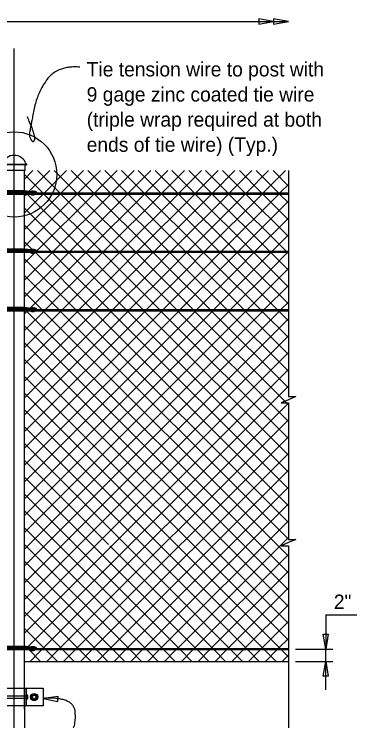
# Model space of a CAD drawing. Extents: x 0 to 41, y -96 to 25.
# Drawn here: x 25.32 to 30.13, y 14.8 to 24.71 of the extents above; entities that cross this region are included whole.
import ezdxf

# ---------------------------------------------------------------- set-up
doc = ezdxf.new("R2010")
doc.units = 0
for name, color, linetype in [('CL_Major', 7, 'Continuous'), ('Dimension', 7, 'Continuous'), ('Miscellaneous', 7, 'Continuous'), ('SteelMisc', 7, 'Continuous'), ('SteelMisc_h', 7, 'Continuous'), ('SupstrConc', 7, 'Continuous')]:
    doc.layers.add(name, color=color, linetype=linetype)

msp = doc.modelspace()

# ---------------------------------------------------------------- linework, layer by layer
at = {"layer": 'CL_Major'}
msp.add_line((25.3238, 9.7541), (25.3238, 24.2317), dxfattribs=at)
at = {"layer": 'Dimension'}
for p, q in [((29.6916, 16.2901), (29.6916, 15.8103)), ((29.6916, 16.2901), (30.1268, 16.2901)), ((29.269, 15.8103), (29.7924, 15.8103)), ((29.6916, 15.6384), (29.6916, 15.8103)), ((29.269, 15.6384), (29.7924, 15.6384)), ((29.6916, 15.2407), (29.6916, 15.6384))]:
    msp.add_line(p, q, dxfattribs=at)
for points in [[(14.3237, 24.6092), (15.7874, 24.6092), (15.7874, 24.7126), (15.8324, 24.6092), (15.8774, 24.5059), (15.8774, 24.6092), (29.1682, 24.6092)], [(29.1682, 22.5181), (29.1682, 19.3509), (29.2716, 19.3509), (29.1682, 19.3059), (29.0649, 19.2609), (29.1682, 19.2609), (29.1682, 18.3673)], [(29.1682, 18.3673), (29.1682, 17.3495), (29.2716, 17.3495), (29.1682, 17.3045), (29.0649, 17.2595), (29.1682, 17.2595), (29.1682, 15.0552)], [(29.1682, 15.3052), (29.1682, 13.4544), (29.2716, 13.4544), (29.1682, 13.4094), (29.0649, 13.3644), (29.1682, 13.3644), (29.1682, 11.8219)]]:
    msp.add_lwpolyline(points, dxfattribs=at)
for points in [[(28.96, 24.6092), (28.7517, 24.6445), (28.7517, 24.5739)], [(29.1682, 24.6092), (28.96, 24.6445), (28.96, 24.5739)], [(29.7269, 16.0185), (29.6916, 15.8103), (29.6563, 16.0185)], [(29.6563, 15.4302), (29.6916, 15.6384), (29.7269, 15.4302)], [(25.7298, 15.1203), (25.9358, 15.074), (25.9396, 15.1444)]]:
    msp.add_lwpolyline(points, close=True, dxfattribs=at)
msp.add_circle((25.3237, 22.4656), 0.5976, dxfattribs=at)
for points in [[(26.2434, 23.9706), (25.9247, 23.9905), (25.6433, 23.6016), (25.5506, 23.1056), (25.5288, 23.0034), (25.5886, 22.9037), (25.6333, 22.9933), (25.5089, 23.2726)], [(26.1714, 14.0966), (25.9344, 14.0943), (26.0058, 14.4456), (26.2043, 14.7506), (26.1489, 15.1434), (25.7297, 15.1203)]]:
    msp.add_open_spline(points, degree=2, dxfattribs=at)
at = {"layer": 'Miscellaneous'}
for p, q in [((25.4696, 22.4004), (25.5873, 22.5181)), ((25.5367, 22.2313), (25.8235, 22.5181)), ((25.65, 22.5181), (25.9625, 22.2055)), ((25.7471, 22.2055), (26.0596, 22.5181)), ((25.8857, 22.5181), (26.1983, 22.2055)), ((25.9833, 22.2055), (26.2958, 22.5181)), ((26.1214, 22.5181), (26.434, 22.2055)), ((26.2194, 22.2055), (26.532, 22.5181)), ((26.3571, 22.5181), (26.6697, 22.2055)), ((26.4556, 22.2055), (26.7682, 22.5181)), ((26.5928, 22.5181), (26.9054, 22.2055)), ((26.6918, 22.2055), (27.0043, 22.5181)), ((26.8285, 22.5181), (27.1411, 22.2055)), ((26.928, 22.2055), (27.2405, 22.5181)), ((27.0642, 22.5181), (27.3768, 22.2055)), ((27.1637, 22.2055), (27.4762, 22.5181)), ((27.2999, 22.5181), (27.6125, 22.2055)), ((27.3994, 22.2055), (27.7119, 22.5181)), ((27.5356, 22.5181), (27.8482, 22.2055)), ((27.6351, 22.2055), (27.9476, 22.5181)), ((27.7713, 22.5181), (28.0839, 22.2055)), ((27.8708, 22.2055), (28.1833, 22.5181)), ((28.0075, 22.5181), (28.32, 22.2055)), ((28.1065, 22.2055), (28.419, 22.5181)), ((28.2437, 22.5181), (28.5562, 22.2055)), ((28.3422, 22.2055), (28.6547, 22.5181)), ((28.4799, 22.5181), (28.7924, 22.2055)), ((28.5779, 22.2055), (28.8904, 22.5181)), ((28.716, 22.5181), (29.0286, 22.2055)), ((28.8136, 22.2055), (29.1261, 22.5181)), ((28.9522, 22.5181), (29.1682, 22.302)), ((25.4696, 22.4628), (25.7268, 22.2055)), ((29.0493, 22.2055), (29.1682, 22.3245)), ((25.4717, 22.225), (25.4911, 22.2055)), ((25.5109, 22.2055), (25.5249, 22.2195)), ((25.4696, 21.4557), (26.2047, 22.1908)), ((25.4696, 21.6919), (25.9685, 22.1908)), ((25.4696, 21.928), (25.7323, 22.1908)), ((25.4696, 22.1642), (25.4962, 22.1908)), ((25.5059, 22.1908), (26.3085, 21.3881)), ((25.6422, 21.3921), (26.4409, 22.1908)), ((25.7416, 22.1908), (26.5442, 21.3881)), ((25.8744, 21.3881), (26.677, 22.1908)), ((25.9773, 22.1908), (26.7799, 21.3881)), ((26.1106, 21.3881), (26.9132, 22.1908)), ((26.213, 22.1908), (27.0157, 21.3881)), ((26.3463, 21.3881), (27.1489, 22.1908)), ((26.4487, 22.1908), (27.2514, 21.3881)), ((26.582, 21.3881), (27.3846, 22.1908)), ((26.6844, 22.1908), (27.4871, 21.3881)), ((26.8177, 21.3881), (27.6203, 22.1908)), ((26.9201, 22.1908), (27.7228, 21.3881)), ((27.0534, 21.3881), (27.856, 22.1908)), ((27.1558, 22.1908), (27.9585, 21.3881)), ((27.2891, 21.3881), (28.0917, 22.1908)), ((27.3915, 22.1908), (28.1942, 21.3881)), ((27.5248, 21.3881), (28.3274, 22.1908)), ((27.6272, 22.1908), (28.4299, 21.3881)), ((27.7605, 21.3881), (28.5631, 22.1908)), ((27.8629, 22.1908), (28.6656, 21.3881)), ((27.9962, 21.3881), (28.7988, 22.1908)), ((28.0986, 22.1908), (28.9013, 21.3881)), ((28.2319, 21.3881), (29.0345, 22.1908)), ((28.3348, 22.1908), (29.1374, 21.3881)), ((28.571, 22.1908), (29.1682, 21.5935)), ((28.8071, 22.1908), (29.1682, 21.8297)), ((29.0433, 22.1908), (29.1682, 22.0659)), ((28.4676, 21.3881), (29.1682, 22.0888)), ((25.4696, 21.9914), (26.0728, 21.3881)), ((28.7033, 21.3881), (29.1682, 21.8531)), ((25.4696, 21.7557), (25.8371, 21.3881)), ((28.939, 21.3881), (29.1682, 21.6174)), ((25.4696, 21.52), (25.5766, 21.413)), ((25.4696, 20.9833), (25.8596, 21.3734)), ((25.4696, 21.2195), (25.6235, 21.3734)), ((25.6162, 21.3734), (26.4196, 20.57)), ((25.8519, 21.3734), (26.0868, 21.1385)), ((25.8609, 21.1385), (26.0958, 21.3734)), ((26.0876, 21.3734), (26.3225, 21.1385)), ((26.0966, 21.1385), (26.3315, 21.3734)), ((26.3233, 21.3734), (26.5582, 21.1385)), ((26.3323, 21.1385), (26.5672, 21.3734)), ((26.559, 21.3734), (26.7939, 21.1385)), ((26.568, 21.1385), (26.8029, 21.3734)), ((26.7947, 21.3734), (27.0296, 21.1385)), ((26.8037, 21.1385), (27.0386, 21.3734)), ((27.0304, 21.3734), (27.2653, 21.1385)), ((27.0394, 21.1385), (27.2743, 21.3734)), ((27.2661, 21.3734), (27.501, 21.1385)), ((27.2751, 21.1385), (27.51, 21.3734)), ((27.5018, 21.3734), (27.7367, 21.1385)), ((27.5108, 21.1385), (27.7457, 21.3734)), ((27.7375, 21.3734), (27.9724, 21.1385)), ((27.7465, 21.1385), (27.9814, 21.3734)), ((27.9732, 21.3734), (28.2081, 21.1385)), ((27.9822, 21.1385), (28.2171, 21.3734)), ((28.2089, 21.3734), (28.4438, 21.1385)), ((28.2179, 21.1385), (28.4528, 21.3734)), ((28.4446, 21.3734), (28.6795, 21.1385)), ((28.4536, 21.1385), (28.6885, 21.3734)), ((28.6803, 21.3734), (28.9152, 21.1385)), ((28.6893, 21.1385), (28.9242, 21.3734)), ((28.916, 21.3734), (29.1682, 21.1212)), ((28.925, 21.1385), (29.1599, 21.3734)), ((29.1522, 21.3734), (29.1682, 21.3573)), ((25.4696, 21.2843), (25.5918, 21.162)), ((25.4696, 21.2843), (26.1839, 20.57)), ((25.4696, 20.7472), (25.8462, 21.1237)), ((25.5526, 20.5944), (26.0966, 21.1385)), ((25.7638, 20.57), (26.3323, 21.1385)), ((25.9995, 20.57), (26.568, 21.1385)), ((26.0868, 21.1385), (26.6553, 20.57)), ((26.2352, 20.57), (26.8037, 21.1385)), ((26.3225, 21.1385), (26.891, 20.57)), ((26.4709, 20.57), (27.0394, 21.1385)), ((26.5582, 21.1385), (27.1267, 20.57)), ((26.7066, 20.57), (27.2751, 21.1385)), ((26.7939, 21.1385), (27.3624, 20.57)), ((26.9423, 20.57), (27.5108, 21.1385)), ((27.0296, 21.1385), (27.5981, 20.57)), ((27.178, 20.57), (27.7465, 21.1385)), ((27.2653, 21.1385), (27.8338, 20.57)), ((27.4137, 20.57), (27.9822, 21.1385)), ((27.501, 21.1385), (28.0695, 20.57)), ((27.6494, 20.57), (28.2179, 21.1385)), ((27.7367, 21.1385), (28.3052, 20.57)), ((27.8851, 20.57), (28.4536, 21.1385)), ((27.9724, 21.1385), (28.5409, 20.57)), ((28.1208, 20.57), (28.6893, 21.1385)), ((28.2081, 21.1385), (28.7766, 20.57)), ((28.3565, 20.57), (28.925, 21.1385)), ((28.4438, 21.1385), (29.0123, 20.57)), ((28.5922, 20.57), (29.1682, 21.146)), ((28.6795, 21.1385), (29.1682, 20.6498)), ((28.9152, 21.1385), (29.1682, 20.8855)), ((25.4696, 21.0486), (25.9482, 20.57)), ((28.8279, 20.57), (29.1682, 20.9103)), ((25.4696, 20.8129), (25.7125, 20.57)), ((29.0636, 20.57), (29.1682, 20.6746)), ((25.4696, 20.5772), (25.4768, 20.57)), ((25.4696, 18.1544), (27.8704, 20.5552)), ((25.4696, 18.6258), (27.3989, 20.5552)), ((25.4696, 19.0972), (26.9275, 20.5552)), ((25.4696, 19.5686), (26.4561, 20.5552)), ((25.4696, 17.683), (28.3418, 20.5552)), ((25.4696, 17.2116), (28.8132, 20.5552)), ((25.4696, 19.8043), (26.2204, 20.5552)), ((25.4696, 19.3329), (26.6918, 20.5552)), ((25.4696, 18.8615), (27.1632, 20.5552)), ((25.4696, 18.3901), (27.6347, 20.5552)), ((25.4696, 17.9187), (28.1061, 20.5552)), ((25.4696, 17.4473), (28.5775, 20.5552)), ((25.4696, 16.9759), (29.0489, 20.5552)), ((25.4696, 20.0401), (25.9847, 20.5552)), ((25.4696, 20.5115), (25.5133, 20.5552)), ((25.474, 20.2802), (25.749, 20.5552)), ((25.4916, 20.5552), (29.1682, 16.8785)), ((25.5281, 20.57), (25.5406, 20.5824)), ((25.7273, 20.5552), (29.1682, 17.1142)), ((25.963, 20.5552), (29.1682, 17.3499)), ((26.1987, 20.5552), (29.1682, 17.5857)), ((26.4344, 20.5552), (29.1682, 17.8214)), ((26.6701, 20.5552), (29.1682, 18.0571)), ((26.9058, 20.5552), (29.1682, 18.2928)), ((27.1415, 20.5552), (29.1682, 18.5285)), ((27.3772, 20.5552), (29.1682, 18.7642)), ((27.6129, 20.5552), (29.1682, 18.9999)), ((27.8486, 20.5552), (29.1682, 19.2356)), ((28.0843, 20.5552), (29.1682, 19.4713)), ((28.32, 20.5552), (29.1682, 19.707)), ((28.5557, 20.5552), (29.1682, 19.9427)), ((28.7914, 20.5552), (29.1682, 20.1784)), ((29.0271, 20.5552), (29.1682, 20.4141)), ((25.4696, 16.7402), (29.1682, 20.4389)), ((25.4696, 20.3415), (29.1682, 16.6428)), ((25.4696, 16.5045), (29.1682, 20.2032)), ((25.4696, 20.1058), (29.1682, 16.4071)), ((25.4696, 16.2688), (29.1682, 19.9675)), ((25.4696, 19.8701), (29.1682, 16.1714)), ((25.4696, 16.0331), (29.1682, 19.7318)), ((25.4696, 19.6344), (29.1682, 15.9357)), ((25.5183, 15.8462), (29.1682, 19.4961)), ((25.4696, 19.3987), (29.0506, 15.8177)), ((25.7255, 15.8177), (29.1682, 19.2603)), ((25.4696, 19.163), (28.8149, 15.8177)), ((25.9612, 15.8177), (29.1682, 19.0246)), ((25.4696, 18.9273), (28.5792, 15.8177)), ((26.1969, 15.8177), (29.1682, 18.7889)), ((25.4696, 18.6916), (28.3435, 15.8177)), ((26.4326, 15.8177), (29.1682, 18.5532)), ((25.4696, 18.4559), (26.6482, 17.2773)), ((26.6683, 15.8177), (29.1682, 18.3175)), ((25.4696, 18.2202), (27.8721, 15.8177)), ((26.904, 15.8177), (29.1682, 18.0818)), ((25.4696, 17.9845), (27.6364, 15.8177)), ((27.1397, 15.8177), (29.1682, 17.8461)), ((25.4696, 17.7488), (27.4007, 15.8177)), ((27.3754, 15.8177), (29.1682, 17.6104)), ((25.4696, 17.5131), (27.165, 15.8177)), ((27.6112, 15.8177), (29.1682, 17.3747)), ((25.4696, 17.2774), (26.9293, 15.8177)), ((26.6659, 17.2595), (28.1078, 15.8177)), ((27.8469, 15.8177), (29.1682, 17.139)), ((25.4696, 17.0417), (26.6936, 15.8177)), ((28.0826, 15.8177), (29.1682, 16.9033)), ((25.4696, 16.8059), (26.4579, 15.8177)), ((28.3183, 15.8177), (29.1682, 16.6676)), ((25.4696, 16.5702), (26.2222, 15.8177)), ((28.554, 15.8177), (29.1682, 16.4319)), ((25.4696, 16.3345), (25.9865, 15.8177)), ((28.7897, 15.8177), (29.1682, 16.1962)), ((25.4696, 16.0988), (25.7508, 15.8177)), ((29.0254, 15.8177), (29.1682, 15.9605)), ((25.4696, 15.8631), (25.4823, 15.8504)), ((25.4696, 15.7974), (25.4751, 15.8029)), ((25.4898, 15.8177), (25.5058, 15.8337)), ((25.4983, 15.8344), (25.5151, 15.8177)), ((25.5298, 15.8029), (25.6943, 15.6384)), ((25.5463, 15.6384), (25.7108, 15.8029)), ((25.7655, 15.8029), (25.93, 15.6384)), ((25.782, 15.6384), (25.9465, 15.8029)), ((26.0012, 15.8029), (26.1657, 15.6384)), ((26.0177, 15.6384), (26.1822, 15.8029)), ((26.2369, 15.8029), (26.4014, 15.6384)), ((26.2534, 15.6384), (26.4179, 15.8029)), ((26.4726, 15.8029), (26.6371, 15.6384)), ((26.4891, 15.6384), (26.6536, 15.8029)), ((26.7083, 15.8029), (26.8728, 15.6384)), ((26.7248, 15.6384), (26.8893, 15.8029)), ((26.944, 15.8029), (27.1085, 15.6384)), ((26.9605, 15.6384), (27.125, 15.8029)), ((27.1797, 15.8029), (27.3442, 15.6384)), ((27.1962, 15.6384), (27.3607, 15.8029)), ((27.4154, 15.8029), (27.5799, 15.6384)), ((27.4319, 15.6384), (27.5964, 15.8029)), ((27.6511, 15.8029), (27.8156, 15.6384)), ((27.6676, 15.6384), (27.8321, 15.8029)), ((27.8868, 15.8029), (28.0513, 15.6384)), ((27.9033, 15.6384), (28.0678, 15.8029)), ((28.1225, 15.8029), (28.287, 15.6384)), ((28.139, 15.6384), (28.3035, 15.8029)), ((28.3582, 15.8029), (28.5227, 15.6384)), ((28.3747, 15.6384), (28.5392, 15.8029)), ((28.5939, 15.8029), (28.7584, 15.6384)), ((28.6104, 15.6384), (28.7749, 15.8029)), ((28.8296, 15.8029), (28.9941, 15.6384)), ((28.8461, 15.6384), (29.0106, 15.8029)), ((29.0653, 15.8029), (29.1682, 15.7)), ((29.0818, 15.6384), (29.1682, 15.7248))]:
    msp.add_line(p, q, dxfattribs=at)
at = {"layer": 'SteelMisc'}
for p, q in [((25.1514, 22.6101), (25.496, 22.6101)), ((25.496, 22.5978), (25.1514, 22.5978)), ((25.4778, 22.5181), (25.4778, 22.5978)), ((25.4778, 22.5181), (25.1697, 22.5181)), ((25.4696, 14.97), (25.4696, 22.5181)), ((25.1779, 22.2381), (25.4691, 22.2398)), ((25.1779, 22.2236), (25.4691, 22.2253)), ((25.4691, 22.2398), (25.561, 22.2283)), ((25.4691, 22.2253), (25.561, 22.2158)), ((25.4696, 22.2055), (25.55, 22.2055)), ((25.6204, 22.2055), (25.6356, 22.2055)), ((25.6441, 22.2055), (29.1682, 22.2055)), ((25.4696, 22.1908), (25.5527, 22.1908)), ((25.6154, 22.1908), (29.1682, 22.1908)), ((25.1779, 21.4207), (25.4691, 21.4224)), ((25.1779, 21.4062), (25.4691, 21.4079)), ((25.4691, 21.4224), (25.561, 21.4109)), ((25.4691, 21.4079), (25.561, 21.3984)), ((25.4696, 21.3881), (25.55, 21.3881)), ((25.4696, 21.3734), (25.5527, 21.3734)), ((25.6154, 21.3734), (29.1682, 21.3734)), ((25.6204, 21.3881), (25.6356, 21.3881)), ((25.6441, 21.3881), (29.1682, 21.3881)), ((25.1779, 20.6026), (25.4691, 20.6043)), ((25.1779, 20.5881), (25.4691, 20.5897)), ((25.4691, 20.6043), (25.5668, 20.5927)), ((25.4691, 20.5897), (25.5612, 20.5803)), ((25.4696, 20.57), (25.55, 20.57)), ((25.4696, 20.5552), (25.5527, 20.5552)), ((25.6154, 20.5552), (29.1682, 20.5552)), ((25.6204, 20.57), (25.6356, 20.57)), ((25.6441, 20.57), (29.1682, 20.57)), ((25.1779, 15.8503), (25.4691, 15.852)), ((25.1779, 15.8358), (25.4691, 15.8374)), ((25.4691, 15.852), (25.5634, 15.8408)), ((25.4691, 15.8374), (25.5612, 15.828)), ((25.4696, 15.8177), (25.55, 15.8177)), ((25.4696, 15.8029), (25.5526, 15.8029)), ((25.6154, 15.8029), (29.1682, 15.8029)), ((25.6203, 15.8177), (25.6356, 15.8177)), ((25.644, 15.8177), (29.1682, 15.8177)), ((29.1682, 15.8177), (29.1682, 15.8029)), ((24.9178, 15.2635), (25.7297, 15.2635)), ((25.4904, 15.2635), (25.4904, 15.0135)), ((25.7297, 15.2635), (25.7297, 15.0135)), ((25.4967, 15.1688), (25.4906, 15.1688)), ((25.4967, 15.1688), (25.4967, 15.1082)), ((25.5114, 15.1645), (25.4967, 15.1645)), ((25.4967, 15.1082), (25.4906, 15.1082)), ((25.5115, 15.1515), (25.4967, 15.1515)), ((25.5115, 15.1255), (25.4967, 15.1255)), ((25.5114, 15.1125), (25.4967, 15.1125)), ((25.5165, 15.1191), (25.5165, 15.158)), ((25.7297, 15.0135), (24.9178, 15.0135)), ((25.4696, 15.0135), (25.4696, 13.7635))]:
    msp.add_line(p, q, dxfattribs=at)
msp.add_lwpolyline([(25.5831, 15.1761), (25.6264, 15.1761), (25.6481, 15.1385), (25.6264, 15.101), (25.5831, 15.101), (25.5614, 15.1385)], close=True, dxfattribs=at)
for radius in [0.05, 0.025]:
    msp.add_circle((25.6047, 15.1385), radius, dxfattribs=at)
for centre, radius, start, end in [((25.4959, 22.6038), 0.00613, 271.1647, 88.8353), ((25.5097, 15.158), 0.00673, 285.7823, 75.54039), ((25.5097, 15.1191), 0.00674, 284.48908, 74.18889), ((25.4968, 15.1385), 0.0196, 318.62797, 41.37203)]:
    msp.add_arc(centre, radius, start, end, dxfattribs=at)
for centre, major_axis, ratio, start_param, end_param in [((25.3244, 22.569), (0.1711, 0), 0.957868, 0.252602, 2.888574), ((25.5748, 22.202), (-0.0251, 0), 0.957868, 5.640694, 6.136824), ((25.5644, 22.2039), (0.0303, -0.0108), 0.724765, 0.058937, 1.929515), ((25.5593, 22.191), (0.0259, 0), 0.957868, 1.031384, 1.505671), ((25.575, 22.2033), (-0.0119, 0), 0.957868, 5.149694, 6.840495), ((25.575, 22.2033), (-0.0119, 0), 0.957868, 0.560069, 0.643501), ((25.5778, 22.2021), (-0.0295, 0), 0.957868, 2.287002, 5.15055), ((25.5734, 22.1975), (0.00795, 0), 0.957868, 3.283494, 6.243757), ((25.5745, 22.1953), (-0.0206, -0.0021), 0.798607, 1.063032, 2.96375), ((25.5677, 22.1999), (0.0139, 0), 0.957868, 6.080589, 7.491112), ((25.5966, 22.2075), (-0.023, 0), 0.957868, 3.422131, 5.0491), ((25.6091, 22.193), (-0.0373, 0), 0.957868, 3.175144, 4.855322), ((25.5955, 22.205), (0.0249, 0), 0.957868, 5.461566, 6.65252), ((25.588, 22.1533), (0.0724, 0), 0.957868, 0.631079, 1.150052), ((25.5748, 22.202), (-0.0251, 0), 0.957868, 0.487549, 0.759758), ((25.5819, 22.2141), (-0.0391, 0), 0.957868, 0.868504, 1.149078), ((25.588, 22.1953), (-0.0206, -0.0021), 0.798607, 1.113032, 1.956656), ((25.5941, 22.201), (-0.0231, 0), 0.957868, 1.44404, 2.487779), ((25.5644, 21.3865), (0.0303, -0.0108), 0.724765, 0.058937, 1.929515), ((25.5778, 21.3847), (-0.0295, 0), 0.957868, 2.287002, 5.15055), ((25.5966, 21.3901), (-0.023, 0), 0.957868, 3.422131, 5.0491), ((25.6091, 21.3756), (-0.0373, 0), 0.957868, 3.175144, 4.855322), ((25.5748, 21.3846), (-0.0251, 0), 0.957868, 5.640694, 6.136824), ((25.5748, 21.3846), (-0.0251, 0), 0.957868, 0.487549, 0.759758), ((25.5819, 21.3967), (-0.0391, 0), 0.957868, 0.868504, 1.149078), ((25.5593, 21.3736), (0.0259, 0), 0.957868, 1.031384, 1.505671), ((25.575, 21.3859), (-0.0119, 0), 0.957868, 5.149694, 6.840495), ((25.575, 21.3859), (-0.0119, 0), 0.957868, 0.560069, 0.643501), ((25.5734, 21.3801), (0.00795, 0), 0.957868, 3.283494, 6.243757), ((25.5745, 21.3779), (-0.0206, -0.0021), 0.798607, 1.063032, 2.96375), ((25.5677, 21.3825), (0.0139, 0), 0.957868, 6.080589, 7.491112), ((25.588, 21.3779), (-0.0206, -0.0021), 0.798607, 1.113032, 1.956656), ((25.5941, 21.3836), (-0.0231, 0), 0.957868, 1.44404, 2.487779), ((25.5955, 21.3876), (0.0249, 0), 0.957868, 5.461566, 6.65252), ((25.588, 21.3359), (0.0724, 0), 0.957868, 0.631079, 1.150052), ((25.5748, 20.5665), (-0.0251, 0), 0.957868, 5.633507, 6.136824), ((25.5748, 20.5665), (-0.0251, 0), 0.957868, 0.487549, 0.751829), ((25.5819, 20.5785), (-0.0391, 0), 0.957868, 0.863445, 1.163876), ((25.5593, 20.5554), (0.0259, 0), 0.957868, 1.031384, 1.505671), ((25.575, 20.5677), (-0.0119, 0), 0.957868, 5.149694, 6.840495), ((25.575, 20.5677), (-0.0119, 0), 0.957868, 0.560069, 0.643501), ((25.5778, 20.5666), (-0.0295, 0), 0.957868, 2.287002, 5.15055), ((25.5644, 20.5684), (0.0303, -0.0108), 0.724765, 5.030292, 8.075668), ((25.5734, 20.5619), (0.00795, 0), 0.957868, 3.252108, 6.243757), ((25.5677, 20.5643), (0.0139, 0), 0.957868, 5.660958, 7.491112), ((25.588, 20.5597), (-0.0206, -0.0021), 0.798607, 1.007662, 1.956656), ((25.5966, 20.5719), (-0.023, 0), 0.957868, 3.422131, 5.0491), ((25.5941, 20.5654), (-0.0231, 0), 0.957868, 1.44404, 2.503632), ((25.6091, 20.5575), (-0.0373, 0), 0.957868, 3.175144, 4.855322), ((25.5955, 20.5694), (0.0249, 0), 0.957868, 5.476514, 6.65252), ((25.588, 20.5178), (0.0724, 0), 0.957868, 0.631079, 1.150052), ((25.5748, 15.8142), (-0.0251, 0), 0.957868, 5.633507, 6.136824), ((25.5748, 15.8142), (-0.0251, 0), 0.957868, 0.487549, 0.751829), ((25.5818, 15.8262), (-0.0391, 0), 0.957868, 0.863445, 1.149078), ((25.5593, 15.8031), (0.0259, 0), 0.957868, 1.031384, 1.505671), ((25.575, 15.8154), (-0.0119, 0), 0.957868, 5.149694, 6.840495), ((25.5667, 15.8165), (0.0303, -0.0108), 0.724765, 5.75303, 8.212701), ((25.575, 15.8154), (-0.0119, 0), 0.957868, 0.560069, 0.643501), ((25.5733, 15.8096), (0.00795, 0), 0.957868, 3.252108, 6.243757), ((25.5745, 15.8074), (-0.0206, -0.0021), 0.798607, 1.063032, 2.262079), ((25.5778, 15.8143), (-0.0295, 0), 0.957868, 2.287002, 5.097821), ((25.5677, 15.812), (0.0139, 0), 0.957868, 5.660958, 7.491112), ((25.5879, 15.8074), (-0.0206, -0.0021), 0.798607, 1.113032, 1.956656), ((25.5966, 15.8196), (-0.023, 0), 0.957868, 3.422131, 5.0491), ((25.594, 15.8131), (-0.0231, 0), 0.957868, 1.44404, 2.503632), ((25.609, 15.8052), (-0.0373, 0), 0.957868, 3.175144, 4.855322), ((25.5954, 15.8171), (0.0249, 0), 0.957868, 5.476514, 6.65252), ((25.5879, 15.7655), (0.0724, 0), 0.957868, 0.631079, 1.150052)]:
    msp.add_ellipse(centre, major_axis=major_axis, ratio=ratio, start_param=start_param, end_param=end_param, dxfattribs=at)
at = {"layer": 'SteelMisc_h'}
for p, q in [((25.1779, 22.2055), (25.4696, 22.2055)), ((25.1779, 22.1908), (25.4696, 22.1908)), ((25.1779, 21.3881), (25.4696, 21.3881)), ((25.1779, 21.3734), (25.4696, 21.3734)), ((25.1779, 20.57), (25.4696, 20.57)), ((25.1779, 20.5552), (25.4696, 20.5552)), ((25.1779, 15.8177), (25.4696, 15.8177)), ((25.1779, 15.8029), (25.4696, 15.8029)), ((25.4696, 15.2635), (25.4696, 15.0135)), ((25.4904, 15.1531), (25.1255, 15.1531)), ((25.1255, 15.1232), (25.4904, 15.1232))]:
    msp.add_line(p, q, dxfattribs=at)
at = {"layer": 'SupstrConc'}
msp.add_line((25.4696, 15.6384), (29.1682, 15.6384), dxfattribs=at)

# ---------------------------------------------------------------- texts
at = {"layer": 'Dimension'}
for s, p in [('Tie tension wire to post with ', (26.3406, 23.8389)), ('9 gage zinc coated tie wire ', (26.3406, 23.4869)), ('(triple wrap required at both ', (26.3406, 23.1349)), ('ends of tie wire) (Typ.)', (26.3406, 22.7829)), ('2"', (29.8043, 16.3733))]:
    msp.add_text(s, height=0.2016, dxfattribs=at).set_placement(p)

doc.saveas('drawing.dxf')
